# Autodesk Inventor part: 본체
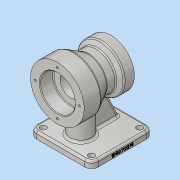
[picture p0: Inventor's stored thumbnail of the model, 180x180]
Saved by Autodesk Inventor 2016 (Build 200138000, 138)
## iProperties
Created: 2019-01
Part Number: 본체
Material: 알루미늄 6061
Document SubType Name: Modeling
Designer: Administrator
Density: 2.7 g/cm^3
Appearance: 알루미늄 - 평지
Mass: 898.816 g
Surface Area: 600.964 cm^2
Volume: 332.895 cm^3
Author: Administrator
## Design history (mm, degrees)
sketch "스케치1"
  geometry: L1 (-46, -46)-(46, -46); L2 (46, -46)-(46, 46); L3 (46, 46)-(-46, 46); L4 (-46, 46)-(-46, -46); L5 (-46, -46)-(46, 46); L6 (46, -46)-(-46, 46); 1 further point
  constraints: 12 end point, 2 midpoint, 2 parallel, 1 horizontal, 1 perpendicular
  dimensions: "d0" = 92 distance of L2.end L3.end; "d1" = 92 distance of L1.end L2.end
extrude "돌출1" new body sketch "스케치1" distance "d2" = 10; taper "d3" = 0 deg
sketch "스케치2"
  geometry: L1 (-51, 80)-(29, 80); L2 (-46, 0)-(46, 0) reference; L3 (29, 80)-(29, 115); L4 (29, 115)-(14, 115); L5 (14, 115)-(8.126, 108); L6 (8.126, 108)-(-5.215, 108); L7 (-5.215, 108)-(-26, 120); L8 (-26, 120)-(-51, 120); L9 (-51, 120)-(-51, 80); L10 (-46, 0)-(-46, 10) reference; 1 further point
  constraints: 16 end point, 2 parallel, 2 perpendicular, 1 horizontal, 1 vertical
  dimensions: "d4" = 80 distance between parallel lines of L2 L1; "d5" = 70 diameter of L4 L1; "d6" = 56 diameter of L6 L1; "d7" = 80 diameter of L8 L1; "d8" = 15 distance of L3.end L4.end; "d9" = 25 distance of L8.end L7.end; "d10" = 5 distance between parallel lines of L10 L9; "d11" = 80 distance between parallel lines of L3 L9; "d12" = 30 deg angle of L6 L7; "d14" = 50 deg angle of L6 L5
revolve "회전1" sketch "스케치2" stored, may be unused: angle "d15" = 90 deg
sketch "스케치3"
  geometry: L1 (-46, -46)-(46, -46) reference; L2 (-46, 46)-(-46, -46) reference; C1 r 16 at (0, -16); 1 further point
  constraints: 1 centre point
  dimensions: "d16" = 30 distance from line of L1 C1.centre; "d17" = 46 distance from line of L2 C1.centre; "d18" = 16 radius of C1
extrude "돌출2" join sketch "스케치3" stored distance "d19" = 0; taper "d20" = 0 deg
sketch "스케치5"
  geometry: L1 (46, 10)-(-46, 10) reference; L2 (36, 10)-(24.753, 34.119); L3 (46, 0)-(46, 10) reference; 1 further point
  constraints: 2 end point, 1 point on line
  dimensions: "d21" = 25 deg angle of L3 L2; "d22" = 10 distance of L1.start L2.start
feature "리브1" sketch "스케치5" dims "d23" = 1, "d24" = 10, "d25" = 0, "d26" = 0, "d27" = 1, "d28" = 1
sketch "스케치6"
  geometry: L1 (-51, 40)-(-51, 120) reference; L2 (-51, 80)-(29, 80); L3 (29, 45)-(29, 115) reference; L4 (29, 80)-(29, 100); L5 (29, 100)-(12, 100); L6 (12, 100)-(12, 96); L7 (12, 96)-(-31, 96); L8 (-31, 96)-(-31, 106); L9 (-31, 106)-(-51, 106); L10 (-51, 106)-(-51, 80); 1 further point
  constraints: 16 end point, 3 perpendicular, 2 midpoint, 2 point on line, 1 collinear, 1 horizontal, 1 vertical
  dimensions: "d29" = 40 diameter of L5 L2; "d30" = 32 diameter of L7 L2; "d31" = 52 diameter of L9 L2; "d32" = 20 distance between parallel lines of L1 L8; "d33" = 17 distance between parallel lines of L3 L6
revolve "회전2" sketch "스케치6" stored, may be unused: angle "d34" = 90 deg
fillet "모깎기1" dims "d35" = 1, "d36" = 0.6
chamfer "모따기1" distance "d37" = 1; stored, may be unused: second distance "d38" = 2, angle "d39" = 45 deg
fillet "모깎기2" dims "d40" = 3, "d41" = 10
fillet "모깎기3" dims "d42" = 3
hole "구멍1" diameter "d45" = 9; stored, may be unused: countersink angle "d49" = 90 deg, drill point angle "d51" = 118 deg; dims "d43" = 10, "d44" = 10, "d46" = 6, "d47" = 4, "d48" = 2, "d50" = 8
sketch "스케치8"
  geometry: L1 (0, 0)-(0, 33); C1 r 40 at (0, 0) reference; 2 further points
  constraints: 2 end point, 1 coincident, 1 vertical
  dimensions: "d52" = 33 distance of L1.start L1.end
hole "구멍2" sketch "스케치8" at (0, 33) diameter "d53" = 3.242; stored, may be unused: countersink angle "d57" = 90 deg, drill point angle "d59" = 118 deg; dims "d54" = 9, "d55" = 4, "d56" = 2, "d58" = 11
sketch "스케치9"
  geometry: L1 (0, 0)-(0, -27.5); C1 r 35 at (0, 0) reference; 2 further points
  constraints: 2 end point, 1 coincident, 1 vertical
  dimensions: "d63" = 27.5 distance of L1.start L1.end
hole "구멍3" sketch "스케치9" at (0, -27.5) diameter "d64" = 3.242; stored, may be unused: countersink angle "d68" = 90 deg, drill point angle "d70" = 118 deg; dims "d65" = 9, "d66" = 4, "d67" = 2, "d69" = 11
sketch "스케치10"
  geometry: L1 (0, 0)-(0, 72) reference; L2 (-7, -10)-(0, -10) reference; 2 further points
  constraints: 1 other
  dimensions: "d74" = 4 distance from line of L1 point (-4, 36); "d75" = 46 distance from line of L2 point (-4, 36)
feature "엠보싱1" sketch "스케치10" dims "d0" = 92, "d1" = 92, "d15" = 90 deg, "d76" = 0.5, "d77" = 0
feature "분할1"
node "솔리드1"
mirror "대칭1"
mirror "대칭2"
pattern_circular "원형 패턴1" dims angle "d61" = 360 deg
pattern_circular "원형 패턴2" dims angle "d72" = 360 deg
